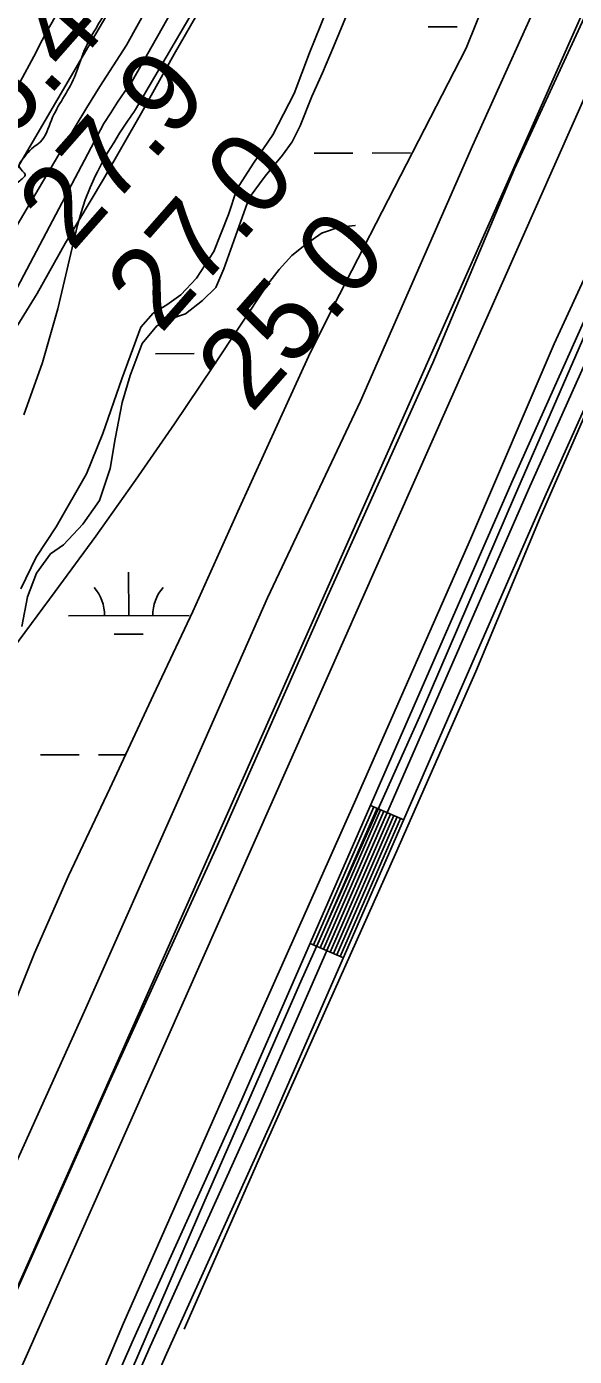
# Model space of a CAD drawing. Extents: x 3324104 to 3361979, y 612876 to 638273.
# Drawn here: x 3339336 to 3339791, y 620863 to 621966 of the extents above; entities that cross this region are included whole.
import ezdxf

# ---------------------------------------------------------------- set-up
doc = ezdxf.new("R2010")
doc.units = 0
for name, color, linetype in [('V-FLOD-BASE', 7, 'Continuous'), ('V-LEVE-TOET', 7, 'Continuous'), ('V-RIVR-EDGE', 7, 'Continuous'), ('V-RIVR-RANG', 7, 'Continuous'), ('V-ROAD-CNTR', 7, 'Continuous'), ('V-SITE-VEGE', 7, 'Continuous'), ('V-SURV-LINE', 7, 'Continuous'), ('V-TOPO-DPTH', 7, 'Continuous'), ('V-TOPO-MAJR', 7, 'Continuous'), ('V-TOPO-MINR', 7, 'Continuous'), ('V-TOPO-SHOR', 7, 'Continuous'), ('V-WETL-SWMP', 7, 'Continuous')]:
    doc.layers.add(name, color=color, linetype=linetype)

msp = doc.modelspace()

# ---------------------------------------------------------------- linework, layer by layer
at = {"layer": 'V-FLOD-BASE'}
msp.add_lwpolyline([(3339312.7, 620882.4), (3339404.9, 621089.8), (3339494.8, 621286.7), (3339586.4, 621493.4), (3339673.4, 621686.8), (3339741.3, 621847.5), (3339817, 622012.2), (3339917.6, 622243.4), (3340054, 622530.2), (3340122.8, 622669), (3340197.7, 622825.3), (3340261.4, 622955.1), (3340303.3, 623031), (3340345.5, 623087.2), (3340405.7, 623158.4), (3340514.4, 623282.9), (3340676.8, 623471.8)], dxfattribs=at)
at = {"layer": 'V-LEVE-TOET'}
for points in [[(3339416.8, 620890.1), (3339510.6, 621102.4), (3339609.6, 621324.5), (3339704.8, 621540.3), (3339774.2, 621702.3), (3339864.8, 621898.5), (3339953.2, 622091.1), (3340054.1, 622308.9), (3340149.8, 622511.3), (3340261.8, 622746.5), (3340341.6, 622906.9), (3340382.1, 622977.2), (3340453.4, 623072.9), (3340537.4, 623166.2), (3340664.9, 623312.1), (3340768.6, 623435.3)], [(3340579.5, 623411.9), (3340453.5, 623271.6), (3340338.8, 623133.2), (3340263.9, 623034), (3340226.3, 622965.8), (3340182, 622876.5), (3340112.2, 622727.8), (3339988.7, 622478.8), (3339907.9, 622310.7), (3339844.7, 622171.7), (3339774.1, 622016.8), (3339706.5, 621866.6), (3339613.4, 621655), (3339536.3, 621491.7), (3339464, 621327.6), (3339384.4, 621148.9), (3339298.2, 620958.3), (3339251.4, 620856.3)], [(3339416.8, 620890.1), (3339301.7, 620617.7), (3339132.1, 620236.2), (3338997.8, 619937.5), (3338847.2, 619604.6), (3338653.6, 619200.7), (3338465.7, 618809.4), (3338277.7, 618431.6), (3338230.9, 618332.4), (3338222.5, 618294.5), (3338221.2, 618274.4)]]:
    msp.add_lwpolyline(points, dxfattribs=at)
at = {"layer": 'V-RIVR-EDGE'}
msp.add_spline([(3338849.5, 620833.7), (3338863.9, 620858.4), (3338873.2, 620877), (3338879.5, 620892.9), (3338887.7, 620911.1), (3338889.2, 620920.8), (3338889.3, 620930.9), (3338889.3, 620936.7), (3338892.8, 620944.8), (3338909.2, 620979.3), (3338928.6, 621017.7), (3338934.9, 621032.8), (3338933, 621036.3), (3338935.3, 621042.1), (3338955.2, 621075.8), (3338956.3, 621080), (3338951.3, 621082.4), (3338952.5, 621087.4), (3338954, 621094.8), (3338957.5, 621099.4), (3338963, 621104.8), (3338961.4, 621110.7), (3338960.7, 621117.6), (3338962.2, 621121.5), (3338980.9, 621151.3), (3338987.5, 621160.2), (3338994.6, 621173), (3339001.6, 621180.4), (3339008.6, 621185.8), (3339012.8, 621191.6), (3339013.6, 621197), (3339013.2, 621200.9), (3339009.8, 621206.7), (3339008.2, 621211.8), (3339009, 621213.7), (3339012.5, 621216.8), (3339014.8, 621221.1), (3339014.9, 621226.5), (3339018.4, 621227.2), (3339028, 621227.6), (3339031.2, 621232.3), (3339035.1, 621243.9), (3339039.8, 621256.3), (3339042.9, 621268.7), (3339045.6, 621270.2), (3339049.9, 621273.7), (3339052.6, 621276.8), (3339055.3, 621283.8), (3339058.5, 621297.7), (3339063.5, 621308.2), (3339066.3, 621319), (3339072.9, 621338), (3339074.5, 621340.7), (3339071.8, 621346.2), (3339071.4, 621350.8), (3339070.6, 621355.9), (3339070.6, 621360.9), (3339074.6, 621374.9), (3339080, 621383.4), (3339091.3, 621402), (3339101.8, 621418.6), (3339106.9, 621432.2), (3339108.9, 621448.5), (3339114.7, 621460.9), (3339121.7, 621472.9), (3339138.1, 621494.5), (3339146.6, 621512.7), (3339150.9, 621515.8), (3339154, 621517), (3339157.5, 621520.5), (3339162.2, 621524.7), (3339162.6, 621530.9), (3339163, 621535.2), (3339166.5, 621539.4), (3339173.9, 621548.4), (3339187.9, 621560), (3339202.3, 621575.4), (3339208.5, 621582), (3339220.9, 621601.4), (3339227.2, 621611.8), (3339228.3, 621618.4), (3339232.6, 621620.7), (3339234.6, 621627.7), (3339234.6, 621632.4), (3339233.8, 621643.2), (3339233.9, 621652.9), (3339235, 621660.7), (3339237.8, 621668.8), (3339245.6, 621681.6), (3339256.4, 621692), (3339259.6, 621702.1), (3339260.4, 621709.5), (3339267.8, 621721.9), (3339275.9, 621735.4), (3339287.3, 621761), (3339293.1, 621772.6), (3339304, 621793.5), (3339318, 621822.9), (3339329.7, 621836.9), (3339335.2, 621843.1), (3339330.5, 621848.9), (3339330.5, 621851.6), (3339333.3, 621855.9), (3339336.4, 621859.7), (3339342.2, 621865.5), (3339347.6, 621869.8), (3339357, 621888), (3339376.1, 621923.6), (3339382.7, 621941.8), (3339386.6, 621950.8), (3339393.2, 621962.8), (3339404.5, 621981.7), (3339427.1, 622013.9), (3339446.2, 622044.5), (3339464.1, 622073.5), (3339479.3, 622102.9), (3339498.8, 622140.9), (3339514.4, 622174.6), (3339531.9, 622205.2), (3339537.7, 622216), (3339537.7, 622219.9), (3339534.7, 622225.7), (3339534.7, 622228.8), (3339534.7, 622231.9), (3339539.7, 622235), (3339547.5, 622242.8), (3339556.8, 622254), (3339556.8, 622259.8), (3339555.7, 622266.4), (3339558.4, 622271.4), (3339563.9, 622273.7), (3339568.6, 622287.7), (3339574, 622293.9), (3339576.3, 622298.5), (3339576.4, 622305.1), (3339577.9, 622309.8), (3339583.4, 622315.6), (3339592.7, 622321.8), (3339605.1, 622339.6), (3339611, 622347.3), (3339621.1, 622355.4), (3339623.8, 622361.6), (3339624.2, 622367.4), (3339624.6, 622374.8), (3339628.1, 622381.4), (3339634.7, 622394.2), (3339652.6, 622417.8), (3339667, 622436.8), (3339680.3, 622456.9), (3339694.3, 622479), (3339705.2, 622499.1), (3339708.7, 622510.7), (3339714.6, 622523.5), (3339723.1, 622538.6), (3339729.4, 622550.2), (3339737.9, 622567.3), (3339738.7, 622571.9), (3339742.2, 622573.5), (3339746.9, 622573.8), (3339748.4, 622577.7), (3339749.2, 622585.1), (3339752, 622591.3), (3339757.8, 622596.7), (3339769.1, 622612.6), (3339778.4, 622620.3), (3339791.2, 622628), (3339795.5, 622636.5), (3339804.1, 622654), (3339820.4, 622682.2), (3339834.5, 622707.8), (3339891.3, 622796.9), (3339910, 622829.4), (3339944.6, 622882.4), (3339978.1, 622936.2), (3339998.7, 622964.9), (3340017.1, 622997.8), (3340021, 623017.2), (3340025.7, 623025.3), (3340038.9, 623040.4), (3340052.9, 623059.4), (3340070.8, 623091.9), (3340085.6, 623112.8), (3340108.6, 623149.2), (3340144.4, 623201.5), (3340174, 623254.2), (3340198.1, 623280.1), (3340221.4, 623307.2), (3340237, 623327.3), (3340244.4, 623342), (3340256.8, 623363.3), (3340272.8, 623384.6), (3340289.1, 623408.2), (3340302.8, 623428.7), (3340311.7, 623438.8), (3340319.5, 623450.4), (3340319.5, 623457.8), (3340325, 623465.9), (3340333.5, 623476.7), (3340341.3, 623483.3), (3340352.2, 623496.5), (3340367.4, 623520.1), (3340394.2, 623560), (3340400.1, 623574.3), (3340403.2, 623588.6), (3340409.1, 623600.7), (3340420.7, 623609.9), (3340437, 623624.6), (3340446.4, 623639.7), (3340451.1, 623650.6), (3340458.1, 623662.2), (3340477.1, 623683.9), (3340488, 623697)], degree=3, dxfattribs=at)
at = {"layer": 'V-ROAD-CNTR'}
for p, q in [((3339649.4, 621307.6), (3339621.9, 621319.6)), ((3339599.3, 621193.1), (3339571.8, 621205.1))]:
    msp.add_line(p, q, dxfattribs=at)
for points in [[(3340841.4, 623447.3), (3340749.1, 623337.6), (3340645.2, 623213.8), (3340452.8, 622986.1), (3340414.2, 622935.4), (3340385.2, 622894.7), (3340357.9, 622843.7), (3340267.3, 622663.5), (3340044.5, 622195.6), (3339766.5, 621575.5), (3339542.5, 621063.3), (3339452.6, 620864.7), (3339341.9, 620612.8)], [(3340726.1, 623356.9), (3340622.3, 623233.1), (3340429.4, 623004.9), (3340390, 622953.2), (3340359.7, 622910.5), (3340331.3, 622857.5), (3340240.4, 622676.7), (3340017.2, 622208.2), (3339739.1, 621587.6), (3339515.1, 621075.5), (3339425.2, 620876.9), (3339314.4, 620624.9)], [(3340737.6, 623347.3), (3340633.8, 623223.5), (3340441.1, 622995.5), (3340402.1, 622944.3), (3340372.4, 622902.6), (3340344.6, 622850.6), (3340253.9, 622670.1), (3340030.9, 622201.9), (3339752.8, 621581.6), (3339528.8, 621069.4), (3339438.9, 620870.8), (3339328.1, 620618.8)], [(3339624.7, 621318.4), (3339574.6, 621203.9)], [(3339627.4, 621317.2), (3339577.3, 621202.7)], [(3339630.2, 621316), (3339580.1, 621201.5)], [(3339632.9, 621314.8), (3339582.8, 621200.3)], [(3339635.6, 621313.6), (3339585.6, 621199.1)], [(3339638.4, 621312.4), (3339588.3, 621197.9)], [(3339641.1, 621311.2), (3339591.1, 621196.7)], [(3339643.9, 621310), (3339593.8, 621195.5)], [(3339646.6, 621308.8), (3339596.6, 621194.3)]]:
    msp.add_lwpolyline(points, dxfattribs=at)
at = {"layer": 'V-SITE-VEGE'}
for p, q in [((3339459, 621942.7), (3339481.8, 621982.4)), ((3339589.9, 621990.5), (3339571.2, 621943.7)), ((3339431.8, 621894), (3339459, 621942.7)), ((3339571.2, 621943.7), (3339558.4, 621910.1)), ((3339558.4, 621910.1), (3339540.7, 621875.9)), ((3339400.2, 621839), (3339431.8, 621894)), ((3339540.7, 621875.9), (3339524.7, 621852.3)), ((3339524.7, 621852.3), (3339510.8, 621830.8)), ((3339368.6, 621786.1), (3339400.2, 621839)), ((3339510.8, 621830.8), (3339503.9, 621809.8)), ((3339503.9, 621809.8), (3339491.9, 621779)), ((3339345.1, 621744.3), (3339368.6, 621786.1)), ((3339491.9, 621779), (3339477.3, 621756.8)), ((3339477.3, 621756.8), (3339464.3, 621743)), ((3339321.6, 621706), (3339345.1, 621744.3)), ((3339464.3, 621743), (3339452.8, 621734.8)), ((3339441.4, 621728), (3339431.2, 621716.2)), ((3339452.8, 621734.8), (3339441.4, 621728)), ((3339431.2, 621716.2), (3339415.4, 621673.5)), ((3339415.4, 621673.5), (3339399.6, 621628)), ((3339399.6, 621628), (3339386.1, 621594.5)), ((3339386.1, 621594.5), (3339361.1, 621550.6)), ((3339361.1, 621550.6), (3339344.3, 621525.6)), ((3339344.3, 621525.6), (3339331.7, 621499.1))]:
    msp.add_line(p, q, dxfattribs=at)
at = {"layer": 'V-SURV-LINE'}
for points in [[(3338630.6, 619347.2), (3339895.2, 622196.6)], [(3339922.6, 622184.4), (3338658, 619335)]]:
    msp.add_lwpolyline(points, dxfattribs=at)
at = {"layer": 'V-TOPO-DPTH'}
msp.add_lwpolyline([(3338714.2, 620540.9), (3339041, 621356.6), (3339393.8, 621959.7), (3339409.7, 621986.5)], dxfattribs=at)
at = {"layer": 'V-TOPO-MAJR'}
for points in [[(3339334.2, 621643.6), (3339349.6, 621687), (3339362.3, 621731.6), (3339378.8, 621800.9), (3339381.6, 621811.5), (3339385, 621821.9), (3339389.1, 621832), (3339393.6, 621842), (3339395.2, 621845.1), (3339399.5, 621853.3), (3339403.9, 621861.4), (3339408.7, 621869.3), (3339413.6, 621877.1), (3339420.8, 621888.1), (3339422.3, 621890.3), (3339423.8, 621892.5), (3339425.4, 621894.7), (3339426.9, 621896.9), (3339772.1, 622486.1)], [(3339609.1, 621800.7), (3339609.1, 621800.7), (3339595.7, 621799.3), (3339582, 621794.5), (3339581.8, 621794.4), (3339568.7, 621785.5), (3339556.6, 621775.6), (3339546, 621764.1), (3339536.4, 621751.6), (3339491.1, 621683.4), (3339459.2, 621636.2), (3339426.9, 621589.3), (3339393.8, 621542.9), (3339360.2, 621496.9), (3339171.3, 621242.2)]]:
    msp.add_lwpolyline(points, dxfattribs=at)
at = {"layer": 'V-TOPO-MINR'}
for points in [[(3338742.8, 620501.6), (3339044.3, 621319.6), (3339375.8, 621881.1), (3339386.5, 621898.5), (3339397.3, 621915.8), (3339408.3, 621933), (3339419.4, 621950.1), (3339730.5, 622511.9), (3339745.4, 622536.1), (3339760.5, 622560.2), (3339775.9, 622584.2), (3339791.4, 622608), (3339834.8, 622673.6), (3339872.3, 622730.1), (3339910.1, 622786.4), (3339948.2, 622842.4), (3339986.6, 622898.3), (3340104.7, 623069.1), (3340117.8, 623088.1), (3340130.9, 623107.2), (3340143.9, 623126.3), (3340156.9, 623145.4), (3340379.3, 623493.6)], [(3338769.6, 620496.1), (3339081.3, 621278.7), (3339093.3, 621303.2), (3339105.7, 621327.5), (3339129.1, 621371.5), (3339400.4, 621885.2), (3339406.2, 621894.1), (3339412, 621902.9), (3339417.9, 621911.7), (3339423.9, 621920.4), (3339761.8, 622517)], [(3338677.2, 620527.9), (3339023.2, 621362.8), (3339036.9, 621385), (3339085.5, 621464.9), (3339344.3, 621944.5), (3339345.6, 621947), (3339346.8, 621949.4), (3339348.1, 621951.8), (3339349.4, 621954.4), (3339351.3, 621957.8), (3339351.9, 621958.9), (3339448.5, 622129.6)], [(3338714.2, 620540.9), (3339041, 621356.6), (3339393.8, 621959.7), (3339409.7, 621986.5)]]:
    msp.add_lwpolyline(points, dxfattribs=at)
at = {"layer": 'V-TOPO-SHOR'}
for points in [[(3340795.8, 623437.1), (3340661, 623279.3), (3340562.3, 623162.4), (3340456.4, 623032.9), (3340385.1, 622939.3), (3340344.1, 622873.9), (3340296.7, 622778.4), (3340211.5, 622601.9), (3340121.1, 622412.8), (3340044, 622250.2), (3339952.6, 622050.5), (3339899, 621930.4), (3339806.1, 621724.5), (3339741.3, 621575.7), (3339663.8, 621396.2), (3339564.1, 621173.4), (3339484.4, 620991.8), (3339417.4, 620836.8)], [(3340760.8, 623351.2), (3340684.3, 623258), (3340594.4, 623148.3), (3340495.3, 623030.3), (3340422.3, 622940), (3340396.3, 622902.3), (3340372, 622863.4), (3340321.7, 622769.8), (3340265.3, 622653.4), (3340218.5, 622552.1), (3340159.4, 622431.6), (3340100.3, 622307.8), (3340037.8, 622174.8), (3339990.6, 622072), (3339936.4, 621953.5), (3339865.2, 621793.9), (3339806.1, 621657.6), (3339762.5, 621558.5), (3339709.2, 621430.6), (3339642.6, 621279.3), (3339531.8, 621032.3), (3339467.1, 620885.2)]]:
    msp.add_lwpolyline(points, dxfattribs=at)
at = {"layer": 'V-WETL-SWMP'}
for p, q in [((3339724.3, 622005), (3339701.1, 621947.7)), ((3339591.1, 621948.8), (3339603.8, 621979.6)), ((3339669.8, 621965.4), (3339693.8, 621965.5)), ((3339582.1, 621927.2), (3339591.1, 621948.8)), ((3339701.1, 621947.7), (3339651.6, 621851.5)), ((3339573.2, 621907.6), (3339582.1, 621927.2)), ((3339563.5, 621883.2), (3339573.2, 621907.6)), ((3339556.8, 621869.9), (3339563.5, 621883.2)), ((3339548.8, 621858.8), (3339556.8, 621869.9)), ((3339575.1, 621860.6), (3339607.1, 621860.7)), ((3339623.1, 621860.7), (3339655.1, 621860.8)), ((3339534.3, 621841.5), (3339548.8, 621858.8)), ((3339651.6, 621851.5), (3339591.1, 621733.7)), ((3339521.2, 621823.5), (3339534.3, 621841.5)), ((3339508.4, 621787.8), (3339521.2, 621823.5)), ((3339500.1, 621764.7), (3339508.4, 621787.8)), ((3339493.4, 621749.3), (3339500.1, 621764.7)), ((3339482.5, 621738.3), (3339493.4, 621749.3)), ((3339468.2, 621727.3), (3339482.5, 621738.3)), ((3339591.1, 621733.7), (3339570.3, 621691.8)), ((3339432.3, 621702.8), (3339444.6, 621717.3)), ((3339444.6, 621717.3), (3339454.6, 621722.7)), ((3339454.6, 621722.7), (3339468.2, 621727.3)), ((3339422.5, 621676.2), (3339432.3, 621702.8)), ((3339443.4, 621694.2), (3339475.4, 621694.3)), ((3339570.3, 621691.8), (3339545.8, 621638.1)), ((3339415.7, 621653.8), (3339422.5, 621676.2)), ((3339410, 621623.6), (3339415.7, 621653.8)), ((3339545.8, 621638.1), (3339511.6, 621563.4)), ((3339405.9, 621599), (3339410, 621623.6)), ((3339396.9, 621572.4), (3339405.9, 621599)), ((3339383, 621552.9), (3339396.9, 621572.4)), ((3339511.6, 621563.4), (3339474.5, 621480.3)), ((3339367.1, 621535.7), (3339383, 621552.9)), ((3339356.3, 621528.2), (3339367.1, 621535.7)), ((3339344.7, 621512.2), (3339356.3, 621528.2)), ((3339337.2, 621492.6), (3339344.7, 621512.2)), ((3339421.2, 621477), (3339421.1, 621513)), ((3339332.4, 621468), (3339337.2, 621492.6)), ((3339371.2, 621476.9), (3339471.2, 621477)), ((3339474.5, 621480.3), (3339441.8, 621411.2)), ((3339409.2, 621461.5), (3339433.2, 621461.5)), ((3339441.8, 621411.2), (3339405.5, 621333.7)), ((3339348, 621361.4), (3339380, 621361.5)), ((3339396, 621361.5), (3339418.5, 621361.5)), ((3339405.5, 621333.7), (3339371.3, 621261.1)), ((3339371.3, 621261.1), (3339343, 621196.9)), ((3339343, 621196.9), (3339316.1, 621129.8))]:
    msp.add_line(p, q, dxfattribs=at)
for centre, start, end in [((3339365.9, 621477.3), 359.3282, 40.8718), ((3339476.4, 621477.5), 139.3282, 180.8718)]:
    msp.add_arc(centre, 35.2, start, end, dxfattribs=at)

# ---------------------------------------------------------------- texts
at = {"layer": 'V-RIVR-RANG'}
for s, p in [('6.4', (3339321.2, 621868.7)), ('27.9', (3339374.3, 621777.6)), ('27.0', (3339447.7, 621709.7)), ('25.0', (3339522.9, 621643.8))]:
    msp.add_text(s, height=67, rotation=48.6183, dxfattribs=at).set_placement(p)

doc.saveas('drawing.dxf')
